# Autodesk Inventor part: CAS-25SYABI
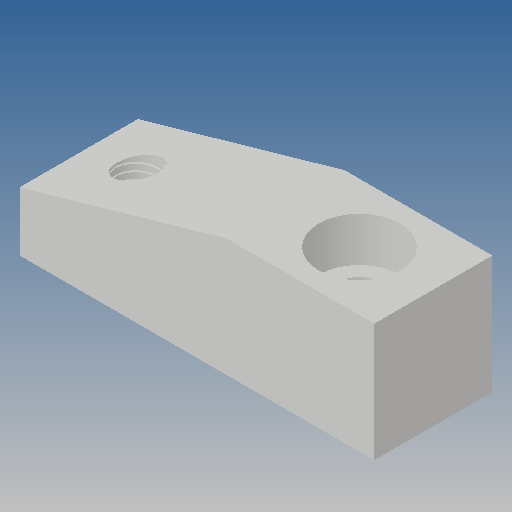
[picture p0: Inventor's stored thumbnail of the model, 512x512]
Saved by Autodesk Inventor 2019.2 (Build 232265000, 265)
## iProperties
Created: 2010-02
Part Number: CAS-25SYABI
Material: Ogólny
Document SubType Name: Modeling
Designer: CADENGINEERING4
Density: 1 g/cm^3
Appearance: Domyślna
Author: CADENGINEERING4
Revision Number: 1LAST_VERSION
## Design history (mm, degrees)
feature "Baza1"
node "Bryła1"
